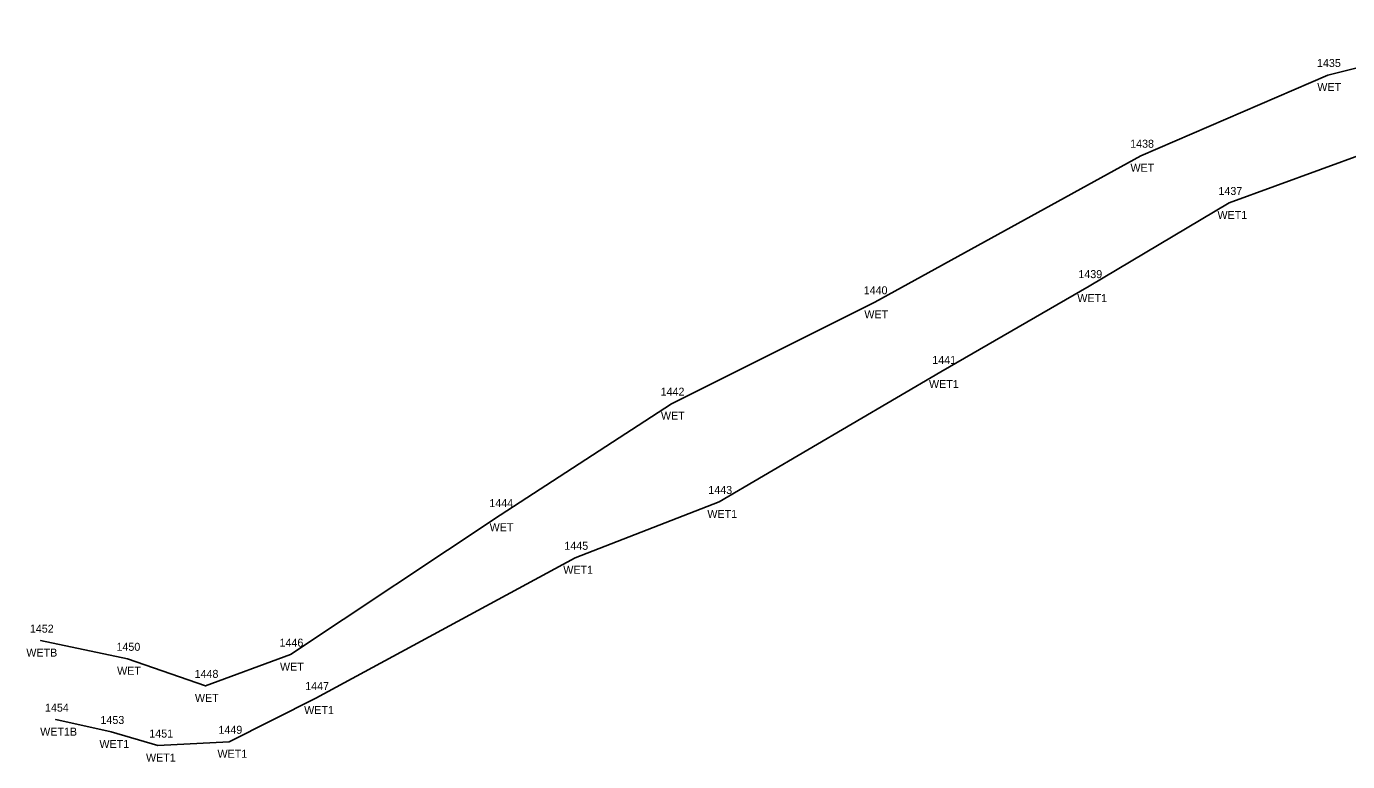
# Model space of a CAD drawing. Extents: x 1967699 to 1968370, y 1117733 to 1117905.
# Drawn here: x 1967870.1 to 1968035.2, y 1117808.1 to 1117900 of the extents above; entities that cross this region are included whole.
import ezdxf

# ---------------------------------------------------------------- set-up
doc = ezdxf.new("R2010")
doc.units = 0
for name, color, linetype in [('RD_EX_H2O_WetLd', 7, 'Continuous'), ('RD_EX_H2O_WetLd_txCode', 7, 'Continuous'), ('RD_SMD_Locator', 7, 'Continuous')]:
    doc.layers.add(name, color=color, linetype=linetype)

msp = doc.modelspace()

# ---------------------------------------------------------------- linework, layer by layer
at = {"layer": 'RD_EX_H2O_WetLd'}
for points in [[(1968056.92, 1117899.97), (1968032.7, 1117893.9), (1968009.37, 1117883.81), (1967976.12, 1117865.5), (1967950.71, 1117852.83), (1967929.31, 1117838.9), (1967903.12, 1117821.47), (1967892.49, 1117817.57), (1967882.77, 1117820.95), (1967871.9, 1117823.22)], [(1968037.49, 1117884.16), (1968020.4, 1117877.91), (1968002.89, 1117867.52), (1967984.36, 1117856.79), (1967956.67, 1117840.55), (1967938.67, 1117833.57), (1967906.3, 1117816.05), (1967895.47, 1117810.58), (1967886.54, 1117810.11), (1967880.72, 1117811.81), (1967873.8, 1117813.35)]]:
    msp.add_lwpolyline(points, dxfattribs=at)
at = {"layer": 'RD_SMD_Locator'}
for centre in [(1968032.7, 1117893.9), (1968009.37, 1117883.81), (1968020.4, 1117877.91), (1968002.89, 1117867.52), (1967976.12, 1117865.5), (1967984.36, 1117856.79), (1967950.71, 1117852.83), (1967956.67, 1117840.55), (1967929.31, 1117838.9), (1967938.67, 1117833.57), (1967871.9, 1117823.22), (1967882.77, 1117820.95), (1967903.12, 1117821.47), (1967892.49, 1117817.57), (1967906.3, 1117816.05), (1967873.8, 1117813.35), (1967880.72, 1117811.81), (1967895.47, 1117810.58), (1967886.54, 1117810.11)]:
    msp.add_circle(centre, 0.001, dxfattribs=at)

# ---------------------------------------------------------------- texts
at = {"layer": 'RD_EX_H2O_WetLd_txCode'}
for s, p in [('1435', (1968031.36, 1117894.9)), ('WET', (1968031.4, 1117891.9)), ('1438', (1968008.02, 1117884.81)), ('WET', (1968008.06, 1117881.81)), ('1437', (1968019.05, 1117878.91)), ('WET1', (1968018.93, 1117875.91)), ('1439', (1968001.55, 1117868.52)), ('1440', (1967974.73, 1117866.5)), ('WET1', (1968001.42, 1117865.52)), ('WET', (1967974.81, 1117863.5)), ('1441', (1967983.3, 1117857.79)), ('WET1', (1967982.89, 1117854.79)), ('1442', (1967949.36, 1117853.83)), ('WET', (1967949.4, 1117850.83)), ('1443', (1967955.32, 1117841.55)), ('1444', (1967927.96, 1117839.9)), ('WET1', (1967955.2, 1117838.55)), ('WET', (1967928, 1117836.9)), ('1445', (1967937.33, 1117834.57)), ('WET1', (1967937.2, 1117831.57)), ('1452', (1967870.56, 1117824.22)), ('WETB', (1967870.12, 1117821.22)), ('1450', (1967881.38, 1117821.95)), ('1446', (1967901.75, 1117822.47)), ('WET', (1967901.81, 1117819.47)), ('WET', (1967881.46, 1117818.95)), ('1448', (1967891.14, 1117818.57)), ('1447', (1967904.96, 1117817.05)), ('WET', (1967891.18, 1117815.57)), ('1454', (1967872.45, 1117814.35)), ('WET1', (1967904.83, 1117814.05)), ('WET1B', (1967871.85, 1117811.35)), ('1453', (1967879.38, 1117812.81)), ('1449', (1967894.12, 1117811.58)), ('WET1', (1967879.25, 1117809.81)), ('1451', (1967885.48, 1117811.11)), ('WET1', (1967885.07, 1117808.11)), ('WET1', (1967894, 1117808.58))]:
    msp.add_text(s, height=1, dxfattribs=at).set_placement(p)

doc.saveas('drawing.dxf')
